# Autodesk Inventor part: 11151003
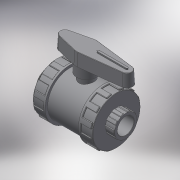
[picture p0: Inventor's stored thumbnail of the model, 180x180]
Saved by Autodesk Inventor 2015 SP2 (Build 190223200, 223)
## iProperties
Created: 2017-11
Part Number: 11151003
Material: Generic
Description: 2/NUT VALVE FEMALE THREAD 3/8" PVC
Document SubType Name: Modeling
Designer: KIM
Density: 1 g/cm^3
Appearance: Default
Author: KIM
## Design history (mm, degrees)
derived "111510.ipt"
feature "Solid1::111510.ipt"
tag "TaggingFeature1"
body "Solid1"
other parameters: "d0" = 71, "d1" = 14.95, "d2" = 45, "d3" = 12, "d4" = 11.96, "d5" = 8.4, "d7" = 20.93, "d8" = 40.5, "d13" = 0.4485, "d23" = 12, "d24" = 43.2, "d25" = 0.299, "d26" = 0.4485, "d27" = 6.75, "d28" = 3.375, "d29" = 9, "d30" = 0, "d35" = 0.4485, "d39" = 22.5, "d45" = 360 deg, "d47" = 0.299, "d50" = 24.75, "d51" = 13.5, "d53" = 0, "d55" = 2.99, "d56" = 1.495, "d57" = 8.4, "d58" = 0, "d59" = 0.4485, "d61" = 360 deg, "d63" = 18, "d64" = 45, "d66" = 65, "d68" = 9, "d69" = 19.5, "d70" = 11.25, "d71" = 3 deg, "d73" = 0.9, "d74" = 26, "d75" = 1.35, "d76" = 0, "d77" = 0.299, "G_" = 14.95, "l_" = 12, "H_" = 71, "K_" = 45, "F_" = 45, "J_" = 65, "d67" = 18, "d72" = 4.5
